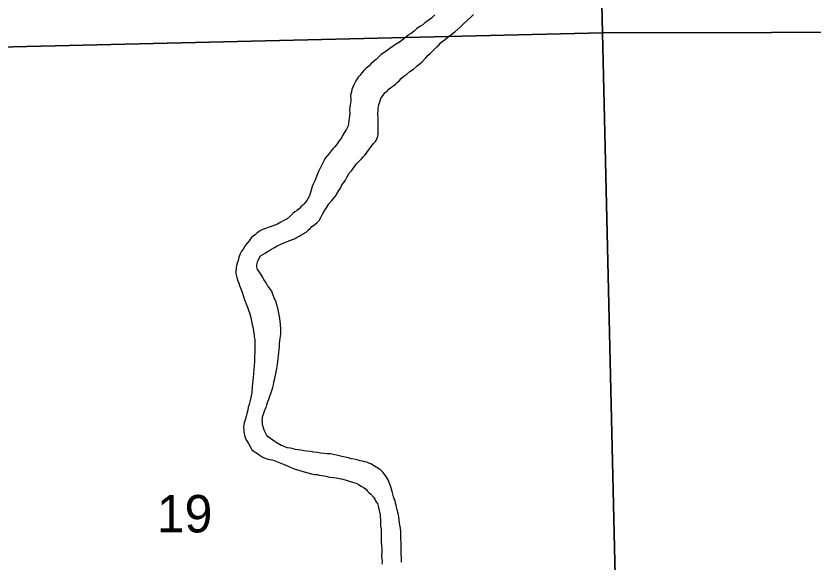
# Model space of a CAD drawing. Extents: x 10.6 to 44.6, y -2.6 to 23.4.
# Drawn here: x 16.54 to 17.431, y 19.247 to 19.857 of the extents above; entities that cross this region are included whole.
import ezdxf

# ---------------------------------------------------------------- set-up
doc = ezdxf.new("R2010")
doc.units = 0
for name, color, linetype in [('GM_X_Major_River', 7, 'Continuous'), ('GM_X_Section', 7, 'Continuous'), ('GM_X_Section_Text', 7, 'Continuous')]:
    doc.layers.add(name, color=color, linetype=linetype)

msp = doc.modelspace()

# ---------------------------------------------------------------- linework, layer by layer
at = {"layer": 'GM_X_Major_River'}
for points in [[(17.00818, 19.85862), (17.00445, 19.85512), (17.00183, 19.85316), (16.99921, 19.8512), (16.99696, 19.84963), (16.99472, 19.84768), (16.99209, 19.84611), (16.98834, 19.84337), (16.98536, 19.84064), (16.982, 19.83791), (16.97861, 19.83593), (16.976, 19.8336), (16.97338, 19.83164), (16.97001, 19.82891), (16.96626, 19.82654), (16.96213, 19.82417), (16.95238, 19.81712), (16.94863, 19.81476), (16.94566, 19.81166), (16.94267, 19.80893), (16.93968, 19.80659), (16.93706, 19.80425), (16.93446, 19.80153), (16.93146, 19.79919), (16.92886, 19.79647), (16.92663, 19.79376), (16.92441, 19.79106), (16.92255, 19.78911), (16.92071, 19.78603), (16.91925, 19.78334), (16.91778, 19.78065), (16.9167, 19.77796), (16.91562, 19.77528), (16.91529, 19.77262), (16.91458, 19.77032), (16.91425, 19.76803), (16.91431, 19.76537), (16.91435, 19.76309), (16.91402, 19.76081), (16.91371, 19.75776), (16.91338, 19.75509), (16.91305, 19.7528), (16.91314, 19.74863), (16.91282, 19.74596), (16.91249, 19.74329), (16.91218, 19.74024), (16.91186, 19.7372), (16.91154, 19.73453), (16.90971, 19.73107), (16.90787, 19.72799), (16.9053, 19.72375), (16.90346, 19.72067), (16.90087, 19.71758), (16.89903, 19.7145), (16.89643, 19.7114), (16.8942, 19.70907), (16.89235, 19.70675), (16.89013, 19.70366), (16.8879, 19.70133), (16.88604, 19.69902), (16.88458, 19.69632), (16.87838, 19.68365), (16.87622, 19.67828), (16.87404, 19.67329), (16.87222, 19.66945), (16.87113, 19.66677), (16.87008, 19.66295), (16.86937, 19.66027), (16.86865, 19.65835), (16.86831, 19.65645), (16.86685, 19.65375), (16.86538, 19.65144), (16.86389, 19.64951)], [(16.94472, 19.74855), (16.94503, 19.7516), (16.94497, 19.75426), (16.94531, 19.75617), (16.94565, 19.75845), (16.94637, 19.76037), (16.94778, 19.76534), (16.95037, 19.76882), (16.95297, 19.77191), (16.95484, 19.77347), (16.95707, 19.7758), (16.95894, 19.77736), (16.96119, 19.77893), (16.96418, 19.78128), (16.96604, 19.78322), (16.96828, 19.78516), (16.97051, 19.78749), (16.9735, 19.79022), (16.97687, 19.79257), (16.98024, 19.79531), (16.98437, 19.79806), (16.98848, 19.80157), (16.99371, 19.80586), (16.99817, 19.81052), (17.0004, 19.81322), (17.00338, 19.81595), (17.00599, 19.81867), (17.00823, 19.82062), (17.01046, 19.82295), (17.0127, 19.82489), (17.01455, 19.82759), (17.01755, 19.82956), (17.02017, 19.83152), (17.02279, 19.83385), (17.02541, 19.83581), (17.02803, 19.83777), (17.03065, 19.83972), (17.03737, 19.84557), (17.04035, 19.84868), (17.04408, 19.85218), (17.04856, 19.85607), (17.05154, 19.85918)], [(16.83307, 19.47137), (16.83338, 19.47479), (16.83369, 19.47784), (16.834, 19.48127), (16.83431, 19.4847), (16.83462, 19.48774), (16.83493, 19.49117), (16.83523, 19.49498), (16.8359, 19.49917), (16.83622, 19.50222), (16.83613, 19.50602), (16.83607, 19.50906), (16.83601, 19.51172), (16.83596, 19.51399), (16.83554, 19.51588), (16.83508, 19.51968), (16.83424, 19.52346), (16.83378, 19.52725), (16.83294, 19.53103), (16.83172, 19.5348), (16.83089, 19.53821), (16.82969, 19.54084), (16.82689, 19.54724), (16.82607, 19.54988), (16.8245, 19.55213), (16.82332, 19.554), (16.82137, 19.55624), (16.81979, 19.55925), (16.81742, 19.56299), (16.81624, 19.56525), (16.81505, 19.56712), (16.81387, 19.569), (16.81152, 19.57237), (16.81034, 19.57424), (16.80951, 19.57726), (16.80946, 19.57954), (16.81052, 19.58375), (16.81344, 19.58951), (16.8187, 19.59228), (16.82132, 19.59424), (16.82358, 19.59543), (16.82583, 19.597), (16.82846, 19.59858), (16.83034, 19.59938), (16.83222, 19.60056), (16.83561, 19.60215), (16.83975, 19.60414), (16.84617, 19.60656), (16.84919, 19.60777), (16.8522, 19.60897), (16.85446, 19.61016), (16.85672, 19.61135), (16.85859, 19.61253), (16.8646, 19.61608), (16.86685, 19.61803), (16.86909, 19.61998), (16.87094, 19.6223), (16.87394, 19.62427), (16.87693, 19.62661), (16.87917, 19.62894), (16.88136, 19.63317), (16.88282, 19.63586), (16.88465, 19.63932), (16.88723, 19.64318), (16.88981, 19.64741), (16.89315, 19.65128), (16.89537, 19.65399), (16.89722, 19.65631), (16.8987, 19.65863), (16.9009, 19.66247), (16.90274, 19.66518), (16.90457, 19.66863), (16.9068, 19.67134), (16.90864, 19.67404), (16.91046, 19.67788), (16.91266, 19.68173), (16.91527, 19.68445), (16.91785, 19.6883), (16.92081, 19.69217), (16.92378, 19.69527), (16.92639, 19.69799), (16.92825, 19.69993), (16.93011, 19.70187), (16.93159, 19.7038), (16.93307, 19.70612), (16.93455, 19.70805), (16.93603, 19.70998), (16.93788, 19.7123), (16.93972, 19.715), (16.94196, 19.71733), (16.94306, 19.71925), (16.9445, 19.72309), (16.94483, 19.72537), (16.94514, 19.72842), (16.94509, 19.73108), (16.94504, 19.73336), (16.94497, 19.7364), (16.94484, 19.74247), (16.9448, 19.74437), (16.94476, 19.74665), (16.94472, 19.74855)], [(16.86389, 19.64951), (16.86241, 19.64758), (16.86055, 19.64564), (16.85869, 19.64408), (16.85682, 19.64214), (16.85458, 19.64019), (16.85195, 19.63861), (16.84971, 19.63666), (16.8471, 19.63432), (16.84337, 19.63082), (16.83886, 19.62845), (16.83622, 19.62725), (16.83246, 19.62489), (16.82945, 19.62368), (16.82643, 19.62248), (16.8234, 19.62165), (16.81925, 19.62004), (16.81624, 19.61883), (16.8136, 19.61763), (16.81172, 19.61646), (16.80984, 19.61527), (16.80799, 19.61333), (16.80536, 19.61138), (16.80312, 19.60943), (16.8009, 19.60634), (16.79831, 19.60324), (16.79609, 19.60015), (16.79425, 19.59708), (16.7924, 19.59475), (16.79095, 19.59168), (16.78951, 19.58785), (16.78844, 19.58441), (16.78736, 19.58134), (16.78666, 19.57867), (16.78634, 19.57562), (16.78603, 19.57219), (16.78608, 19.56991), (16.78735, 19.56386), (16.78816, 19.5616), (16.78936, 19.55896), (16.79018, 19.55632), (16.7914, 19.55255), (16.793, 19.54878), (16.79422, 19.54501), (16.79584, 19.54049), (16.79746, 19.53596), (16.79906, 19.53219), (16.80027, 19.5288), (16.8015, 19.52465), (16.80273, 19.52049), (16.80358, 19.51633), (16.80441, 19.51293), (16.80526, 19.50877), (16.80573, 19.50498), (16.80656, 19.50157), (16.80661, 19.49891), (16.80706, 19.49588), (16.80711, 19.4936), (16.80716, 19.49095), (16.80723, 19.48791), (16.80733, 19.48335), (16.80674, 19.47536), (16.80682, 19.47156), (16.80653, 19.46699), (16.80559, 19.45785), (16.80529, 19.45366), (16.80499, 19.45024), (16.80467, 19.44719), (16.80438, 19.443), (16.80376, 19.43653), (16.80273, 19.43119), (16.80204, 19.42775), (16.80099, 19.42355), (16.79991, 19.42048), (16.79923, 19.41705), (16.79817, 19.41323), (16.79748, 19.40979), (16.79677, 19.40749), (16.79606, 19.4052), (16.79534, 19.4029), (16.79501, 19.40062), (16.7947, 19.39757), (16.79474, 19.39529), (16.79479, 19.39301), (16.79605, 19.38772), (16.79685, 19.38545), (16.79843, 19.38283), (16.80002, 19.37982), (16.80199, 19.37645), (16.80436, 19.37232), (16.80899, 19.36938), (16.81208, 19.36716), (16.81555, 19.36496), (16.81939, 19.36314), (16.8236, 19.36209), (16.82628, 19.36139), (16.82895, 19.36069), (16.83241, 19.35925), (16.83625, 19.35781), (16.84008, 19.35637), (16.8443, 19.35456)], [(16.9708, 19.25546), (16.97074, 19.2585), (16.97066, 19.26192), (16.97059, 19.26534), (16.97051, 19.26913), (16.97043, 19.27293), (16.97034, 19.27711), (16.97025, 19.28129), (16.96979, 19.28508), (16.96934, 19.28849), (16.9689, 19.29114), (16.96845, 19.29455), (16.968, 19.29796), (16.96716, 19.30174), (16.96631, 19.30553), (16.96549, 19.30855), (16.96506, 19.31082), (16.96425, 19.31308), (16.96381, 19.31611), (16.96301, 19.318), (16.9622, 19.32026), (16.96137, 19.32328), (16.96055, 19.3263), (16.95973, 19.32895), (16.9593, 19.33122), (16.9585, 19.3331), (16.95689, 19.33725), (16.95609, 19.33913), (16.95491, 19.341), (16.95372, 19.34326), (16.95176, 19.34587), (16.9502, 19.34774), (16.94787, 19.34997), (16.94556, 19.35144), (16.93669, 19.35695), (16.93439, 19.35766), (16.93247, 19.35876), (16.93017, 19.35947), (16.92749, 19.36017), (16.92482, 19.36049), (16.92138, 19.36156), (16.91832, 19.36225), (16.91489, 19.36256), (16.91182, 19.36363), (16.90799, 19.36469), (16.90456, 19.36537), (16.9015, 19.36607), (16.89844, 19.36676), (16.895, 19.36745), (16.89156, 19.36813), (16.88813, 19.36844), (16.8847, 19.36874), (16.88051, 19.36903), (16.87708, 19.36972), (16.87327, 19.37001), (16.86945, 19.37069), (16.86487, 19.37135), (16.86182, 19.37166), (16.85876, 19.37236), (16.85571, 19.37267), (16.85266, 19.37299), (16.84998, 19.37369), (16.84691, 19.37476), (16.84387, 19.37507), (16.84157, 19.37578), (16.83849, 19.37724), (16.83659, 19.37758), (16.83466, 19.37868), (16.83274, 19.37977), (16.83003, 19.38161), (16.82733, 19.38346), (16.82463, 19.3853), (16.82193, 19.38714), (16.82036, 19.38939), (16.81758, 19.39465), (16.81677, 19.39729), (16.81592, 19.40107), (16.81588, 19.40297), (16.81546, 19.40486), (16.8158, 19.40677), (16.81576, 19.40867), (16.8161, 19.41057), (16.81682, 19.41249), (16.81753, 19.41479), (16.81824, 19.41746), (16.8197, 19.42015), (16.82079, 19.42284), (16.82185, 19.42666), (16.82293, 19.42934), (16.824, 19.43279), (16.82507, 19.43585), (16.82615, 19.43891), (16.82722, 19.44236), (16.82791, 19.44541), (16.82861, 19.44847), (16.82967, 19.45229), (16.83035, 19.45611), (16.83102, 19.4603), (16.83171, 19.46374), (16.83238, 19.46793), (16.83307, 19.47137)], [(16.8443, 19.35456), (16.85121, 19.35167), (16.85734, 19.34952), (16.86232, 19.34811), (16.86652, 19.34706), (16.87035, 19.34601), (16.87417, 19.34533), (16.87684, 19.34501), (16.87914, 19.3443), (16.88181, 19.34398), (16.88486, 19.34366), (16.88792, 19.34297), (16.89059, 19.34227), (16.89516, 19.34199), (16.89822, 19.34129), (16.90166, 19.34061), (16.90548, 19.33993), (16.90931, 19.33887), (16.91352, 19.33744), (16.91735, 19.33639), (16.92041, 19.33531), (16.92311, 19.33385), (16.92581, 19.33201), (16.9285, 19.33055), (16.93159, 19.32872), (16.93277, 19.32684), (16.93471, 19.32498), (16.93665, 19.32312), (16.93976, 19.31977), (16.94133, 19.31753), (16.94253, 19.31489), (16.9441, 19.31264), (16.94493, 19.30962), (16.94703, 19.30017), (16.94708, 19.29789), (16.94751, 19.29524), (16.94757, 19.29258), (16.94763, 19.28992), (16.94768, 19.28726), (16.94814, 19.28385), (16.94822, 19.28005), (16.94828, 19.27701), (16.94835, 19.27359), (16.94844, 19.2698), (16.94852, 19.266), (16.94898, 19.26221), (16.94906, 19.25841), (16.94877, 19.25422), (16.94922, 19.25081), (16.94928, 19.24815), (16.94896, 19.24511)], [(16.97098, 19.2471), (16.97092, 19.25014), (16.97086, 19.2528), (16.9708, 19.25546)]]:
    msp.add_lwpolyline(points, dxfattribs=at)
at = {"layer": 'GM_X_Section'}
for points in [[(18.11709, 20.92473), (18.13938, 19.84048), (17.1955, 19.83846), (17.17051, 20.91202), (17.62631, 20.92202)], [(17.17051, 20.91202), (17.1955, 19.83846), (16.23849, 19.81579), (16.21154, 20.88991), (16.6813, 20.903), (17.15214, 20.91165)], [(16.23849, 19.81579), (17.1955, 19.83846), (17.21979, 18.8008), (16.26575, 18.79438)]]:
    msp.add_lwpolyline(points, close=True, dxfattribs=at)
msp.add_lwpolyline([(18.15917, 19.02628), (18.16459, 18.80313), (17.21979, 18.8008), (17.1955, 19.83846), (18.13938, 19.84048), (18.14543, 19.59131)], dxfattribs=at)

# ---------------------------------------------------------------- texts
at = {"layer": 'GM_X_Section_Text'}
msp.add_text('19', height=0.041856, rotation=0.00001, dxfattribs=at).set_placement((16.69758, 19.28045))

doc.saveas('drawing.dxf')
